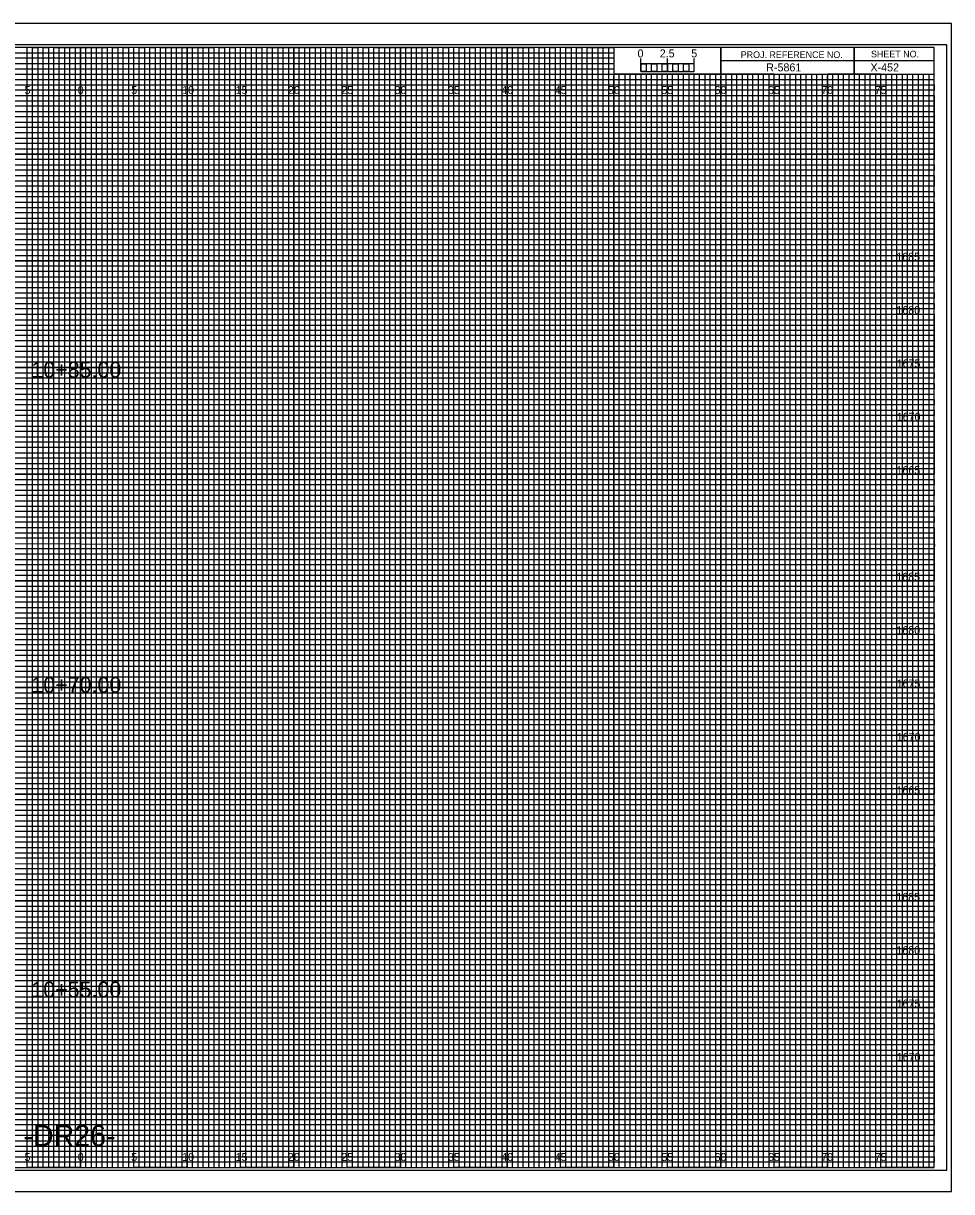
# Model space of a CAD drawing. Extents: x -7 to 162, y -2 to 217.
# Drawn here: x 74.6 to 161.7, y -2.3 to 107.3 of the extents above; entities that cross this region are included whole.
import ezdxf

# ---------------------------------------------------------------- set-up
doc = ezdxf.new("R2010")
doc.units = 0
for name, color, linetype in [('Prop Horizontal Alignment', 7, 'Continuous'), ('Prop XS Alignment Label', 7, 'Continuous'), ('Prop XS Bar Scale Labels', 7, 'Continuous'), ('Prop XS Project Number', 7, 'Continuous'), ('Prop XS Sheet Number', 7, 'Continuous'), ('Raster_Level_0', 7, 'Continuous'), ('Scratch_Level_3', 7, 'Continuous'), ('Sheet Cross Section CELL', 7, 'Continuous'), ('Sheet Cross Section Grid Major CELL', 7, 'Continuous'), ('Sheet Cross Section Grid Middle CELL', 7, 'Continuous'), ('Sheet Cross Section Grid Minor 1 CELL', 7, 'Continuous'), ('Sheet Cross Section Grid Minor 2 CELL', 7, 'Continuous'), ('Sheet Cross Section Scale CELL', 7, 'Continuous'), ('Sheet Cutting Line CELL', 7, 'Continuous'), ('Sheet DOT Grid CELL', 7, 'Continuous'), ('Sheet Plot Border Inside CELL', 7, 'Continuous'), ('Sheet Plot Border Outside CELL', 7, 'Continuous')]:
    doc.layers.add(name, color=color, linetype=linetype)

msp = doc.modelspace()

# ---------------------------------------------------------------- linework, layer by layer
at = {"layer": 'Sheet Cross Section CELL'}
for p, q in [((152.5, 105), (152.5, 102.5)), ((152.5, 102.5), (152.5, 105)), ((160, 103.75), (140, 103.75)), ((140, 103.75), (140, 102.5)), ((140, 102.5), (160, 102.5))]:
    msp.add_line(p, q, dxfattribs=at)
for points in [[(160, 105), (0, 105), (0, 0), (160, 0)], [(140, 105), (130, 105), (130, 102.52), (140, 102.52)], [(160, 105), (140, 105), (140, 102.5), (160, 102.5)]]:
    msp.add_lwpolyline(points, close=True, dxfattribs=at)
at = {"layer": 'Sheet Cross Section Grid Major CELL'}
for p, q in [((75, 105), (70, 105)), ((75, 0), (75, 105)), ((85, 105), (80, 105)), ((80, 105), (80, 0)), ((85, 0), (85, 105)), ((95, 105), (90, 105)), ((90, 105), (90, 0)), ((95, 0), (95, 105)), ((105, 105), (100, 105)), ((100, 105), (100, 0)), ((105, 0), (105, 105)), ((115, 105), (110, 105)), ((110, 105), (110, 0)), ((115, 0), (115, 105)), ((125, 105), (120, 105)), ((120, 105), (120, 0)), ((125, 0), (125, 105)), ((130, 105), (130, 0)), ((135, 0), (135, 102.5)), ((145, 102.5), (140, 102.5)), ((140, 102.5), (140, 0)), ((145, 0), (145, 102.5)), ((155, 102.5), (150, 102.5)), ((150, 102.5), (150, 0)), ((155, 0), (155, 102.5)), ((80, 0), (75, 0)), ((90, 0), (85, 0)), ((100, 0), (95, 0)), ((110, 0), (105, 0)), ((120, 0), (115, 0)), ((130, 0), (125, 0)), ((140, 0), (135, 0)), ((150, 0), (145, 0)), ((160, 0), (155, 0)), ((160, 0), (160, 0))]:
    msp.add_line(p, q, dxfattribs=at)
for points in [[(0, 100), (160, 100), (160, 95), (0, 95)], [(0, 90), (160, 90), (160, 85), (0, 85)], [(0, 80), (160, 80), (160, 75), (0, 75)], [(0, 70), (160, 70), (160, 65), (0, 65)], [(0, 60), (160, 60), (160, 55), (0, 55)], [(0, 50), (160, 50), (160, 45), (0, 45)], [(0, 40), (160, 40), (160, 35), (0, 35)], [(0, 30), (160, 30), (160, 25), (0, 25)], [(0, 20), (160, 20), (160, 15), (0, 15)], [(0, 10), (160, 10), (160, 5), (0, 5)]]:
    msp.add_lwpolyline(points, dxfattribs=at)
at = {"layer": 'Sheet Cross Section Grid Middle CELL'}
for points in [[(72.5, 0), (77.5, 0), (77.5, 105), (82.5, 105), (82.5, 0), (87.5, 0), (87.5, 105), (92.5, 105), (92.5, 0), (97.5, 0), (97.5, 105), (102.5, 105), (102.5, 0), (107.5, 0), (107.5, 105), (112.5, 105), (112.5, 0), (117.5, 0), (117.5, 105), (122.5, 105), (122.5, 0), (127.5, 0), (127.5, 105), (129.97, 105), (130, 105), (130, 102.5), (132.5, 102.5), (132.5, 0), (137.5, 0), (137.5, 102.5), (142.5, 102.5), (142.5, 0), (147.5, 0), (147.5, 102.5), (152.5, 102.5), (152.5, 0), (157.5, 0), (157.5, 102.5)], [(0, 102.5), (137.5, 102.5)], [(0, 92.5), (160, 92.5), (160, 97.5), (0, 97.5)], [(0, 82.5), (160, 82.5), (160, 87.5), (0, 87.5)], [(0, 72.5), (160, 72.5), (160, 77.5), (0, 77.5)], [(0, 62.5), (160, 62.5), (160, 67.5), (0, 67.5)], [(0, 52.5), (160, 52.5), (160, 57.5), (0, 57.5)], [(0, 42.5), (160, 42.5), (160, 47.5), (0, 47.5)], [(0, 32.5), (160, 32.5), (160, 37.5), (0, 37.5)], [(0, 22.5), (160, 22.5), (160, 27.5), (0, 27.5)], [(0, 12.5), (160, 12.5), (160, 17.5), (0, 17.5)], [(0, 2.5), (160, 2.5), (160, 7.5), (0, 7.5)]]:
    msp.add_lwpolyline(points, dxfattribs=at)
at = {"layer": 'Sheet Cross Section Grid Minor 1 CELL'}
for p, q in [((0, 104.5), (130, 104.5)), ((130, 104.5), (130, 103.99)), ((130, 103.99), (0, 103.99)), ((0, 103.5), (130, 103.5)), ((130, 102.95), (0, 102.95)), ((130, 103.5), (130, 102.95)), ((0, 102), (160, 102))]:
    msp.add_line(p, q, dxfattribs=at)
for points in [[(0, 101.5), (135, 101.5), (160, 101.5), (160, 101), (0, 101)], [(0, 100.5), (160, 100.5), (160, 99.5), (0, 99.5)], [(0, 99), (160, 99), (160, 98.5), (0, 98.49)], [(0, 98), (160, 98), (160, 97), (0, 97)], [(0, 96.5), (160, 96.5), (160, 96), (0, 96)], [(0, 95.5), (160, 95.5), (160, 94.5), (0, 94.5)], [(0, 94), (160, 94), (160, 93.5), (0, 93.5)], [(0, 93), (160, 93), (160, 92), (0, 92)], [(0, 91.5), (160, 91.5), (160, 91), (0, 91)], [(0, 90.5), (160, 90.5), (160, 89.5), (0, 89.5)], [(0, 89), (160, 89), (160, 88.5), (0, 88.5)], [(0, 88), (160, 88), (160, 86.98), (160, 86.5), (160, 86), (0, 86)], [(0, 87), (160, 87), (160, 86.5), (0, 86.5)], [(0, 85.5), (160, 85.5), (160, 84.5), (0, 84.52)], [(0, 84.52), (160, 84.5), (160, 84), (0, 84)], [(0, 83.5), (160, 83.5), (160, 83), (0, 83)], [(0, 82), (160, 82), (160, 81.5), (0, 81.5)], [(0, 81), (160, 81), (160, 80.5), (0, 80.5)], [(-0.04, 79.45), (160, 79.45), (160, 78.94), (-0.04, 78.94)], [(0, 78.5), (160, 78.5), (160, 78), (0, 78)], [(0, 77), (160, 77), (160, 76.5), (0, 76.5)], [(0, 76), (160, 76), (160, 75.5), (0, 75.5)], [(0, 74.5), (160, 74.5), (160, 74), (0, 74)], [(0, 73.5), (160, 73.5), (160, 73), (0, 73)], [(0, 72), (160, 72), (160, 71.5), (0, 71.5)], [(0, 71), (160, 71), (160, 70.5), (0, 70.5)], [(0, 69.5), (160, 69.5), (160, 68.99), (0, 69)], [(0, 68.5), (160, 68.5), (160, 68), (0, 68)], [(0, 67), (160, 67), (160, 66.5), (0, 66.5)], [(0, 66), (160, 66), (160, 65.5), (0, 65.5)], [(0, 64.5), (160, 64.5), (160, 64), (0, 64)], [(0, 63.5), (160, 63.5), (160, 63), (0, 63)], [(0, 62), (160, 62), (160, 61.5), (0, 61.5)], [(0, 61), (160, 61), (160, 60.5), (0, 60.5)], [(0, 59.5), (160, 59.5), (160, 59), (0, 59)], [(0, 58.5), (160.03, 58.45), (160, 58), (0, 58)], [(0, 57), (160, 57), (160, 56.5), (0, 56.5)], [(0, 56), (160, 56), (160, 55.5), (0, 55.5)], [(0, 54.5), (160, 54.5), (160, 54), (0, 54)], [(0, 53.5), (160, 53.5), (160, 53), (0, 53)], [(0, 52), (160, 52), (160, 51.5), (0, 51.5)], [(0, 51), (160, 51), (160, 50.5), (0, 50.5)], [(0, 49.5), (160, 49.5), (160, 49), (0, 49)], [(0, 48.5), (160, 48.5), (160, 48), (0, 48)], [(0, 47), (160, 47), (160, 46.5), (0, 46.5)], [(0, 46), (160, 46), (160, 45.5), (0, 45.5)], [(0, 44.5), (160, 44.5), (160, 44), (0, 44)], [(0, 43.5), (160, 43.5), (160, 43), (0, 43)], [(0, 42), (160, 42), (160, 41.5), (0, 41.5)], [(0, 41), (160, 41), (160, 40.5), (0, 40.5)], [(0, 39.5), (160, 39.5), (160, 38.99), (0, 39)], [(0, 38.5), (160, 38.5), (160, 38), (0, 38)], [(0, 37), (160, 37), (160, 36.5), (0, 36.5)], [(0, 36), (160, 36), (160, 35.5), (0, 35.5)], [(0, 34.5), (160, 34.5), (160, 34), (0, 34)], [(0, 33.5), (160, 33.5), (160, 33), (0, 33)], [(0, 32), (160, 32), (160, 31.5), (0, 31.5)], [(0, 31), (160, 31), (160, 30.5), (0, 30.5)], [(0, 29.5), (160, 29.5), (160, 29), (0, 29)], [(0, 28.5), (160.03, 28.46), (160, 28), (0, 28)], [(0, 27), (160, 27), (160, 26.5), (0, 26.5)], [(0, 26), (160, 26), (160, 25.5), (0, 25.5)], [(0, 24.5), (160, 24.5), (160, 24), (0, 24)], [(0, 23.5), (160, 23.5), (160, 23), (0, 23)], [(0, 22), (160, 22), (160, 21.5), (0, 21.5)], [(0, 21), (160, 21), (160, 20.5), (0, 20.5)], [(0, 19.5), (160, 19.5), (160, 19), (0, 19)], [(0, 18.5), (160, 18.5), (160, 18), (0, 18)], [(0, 17), (160, 17), (160, 16.5), (0, 16.5)], [(0, 16), (160, 16), (160, 15.5), (0, 15.5)], [(0, 14.5), (160, 14.5), (160, 14), (0, 14)], [(0, 13.5), (160, 13.5), (160, 13), (0, 13)], [(0, 12), (160, 12), (160, 11.5), (0, 11.5)], [(0, 11), (160, 11), (160, 10.5), (0, 10.5)], [(0, 9.5), (160, 9.5), (160, 9), (0, 9)], [(0, 8.5), (160, 8.5), (160, 8), (0, 8)], [(0, 7), (160, 7), (160, 6.5), (0, 6.5)], [(0, 6), (160, 6), (160, 5.5), (0, 5.5)], [(0, 4.5), (160, 4.5), (160, 4), (0, 4)], [(0, 3.5), (160, 3.5), (160, 3), (0, 3)], [(0, 2), (160, 2), (160, 1.5), (0, 1.5)], [(0, 1), (160, 1), (160, 0.5), (0, 0.5)]]:
    msp.add_lwpolyline(points, dxfattribs=at)
at = {"layer": 'Sheet Cross Section Grid Minor 2 CELL'}
for p, q in [((133.5, 102.5), (133, 102.5)), ((133, 102.5), (133, 0)), ((133.5, 0), (133.5, 102.5)), ((134.5, 102.5), (134, 102.5)), ((134, 102.5), (134, 0)), ((134.5, 0), (134.5, 102.5)), ((133, 0), (132.5, 0)), ((134, 0), (133.5, 0))]:
    msp.add_line(p, q, dxfattribs=at)
for points in [[(75, 0), (75.5, 0), (75.5, 105), (76, 105), (76, 0)], [(76, 0), (76.5, 0), (76.5, 105), (77, 105), (77, 0)], [(77.5, 0), (78, 0), (78, 105), (78.5, 105), (78.5, 0)], [(78.5, 0), (79, 0), (79, 105), (79.5, 105), (79.5, 0)], [(80, 0), (80.5, 0), (80.5, 105), (81, 105), (81, 0)], [(81, 0), (81.5, 0), (81.5, 105), (82, 105), (82, 0)], [(82.5, 0), (83, 0), (83, 105), (83.5, 105), (83.5, 0)], [(83.5, 0), (84, 0), (84, 105), (84.5, 105), (84.5, 0)], [(85, 0), (85.5, 0), (85.5, 105), (86, 105), (86, 0)], [(86, 0), (86.5, 0), (86.5, 105), (87, 105), (87, 0)], [(87.5, 0), (88, 0), (88, 105), (88.5, 105), (88.5, 0)], [(88.5, 0), (89, 0), (89, 105), (89.5, 105), (89.5, 0)], [(90, 0), (90.5, 0), (90.5, 105), (91, 105), (91, 0)], [(91, 0), (91.5, 0), (91.5, 105), (92, 105), (92, 0)], [(92.5, 0), (93, 0), (93, 105), (93.5, 105), (93.5, 0)], [(93.5, 0), (94, 0), (94, 105), (94.5, 105), (94.5, 0)], [(95, 0), (95.5, 0), (95.5, 105), (96, 105), (96, 0)], [(96, 0), (96.5, 0), (96.5, 105), (97, 105), (97, 0)], [(97.5, 0), (98, 0), (98, 105), (98.5, 105), (98.5, 0)], [(98.5, 0), (99, 0), (99, 105), (99.5, 105), (99.5, 0)], [(100, 0), (100.5, 0), (100.5, 105), (101, 105), (101, 0)], [(101, 0), (101.5, 0), (101.5, 105), (102, 105), (102, 0)], [(102.5, 0), (103, 0), (103, 105), (103.5, 105), (103.5, 0)], [(103.5, 0), (104, 0), (104, 105), (104.5, 105), (104.5, 0)], [(105, 0), (105.5, 0), (105.5, 105), (106, 105), (106, 0)], [(106, 0), (106.5, 0), (106.5, 105), (107, 105), (107, 0)], [(107.5, 0), (108, 0), (108, 105), (108.5, 105), (108.5, 0)], [(108.5, 0), (109, 0), (109, 105), (109.5, 105), (109.5, 0)], [(110, 0), (110.5, 0), (110.5, 105), (111, 105), (111, 0)], [(111, 0), (111.5, 0), (111.5, 105), (112, 105), (112, 0)], [(112.5, 0), (113, 0), (113, 105), (113.5, 105), (113.5, 0)], [(113.5, 0), (114, 0), (114, 105), (114.5, 105), (114.5, 0)], [(115, 0), (115.5, 0), (115.5, 105), (116, 105), (116, 0)], [(116, 0), (116.5, 0), (116.5, 105), (117, 105), (117, 0)], [(117.5, 0), (118, 0), (118, 105), (118.5, 105), (118.5, 0)], [(118.5, 0), (119, 0), (119, 105), (119.5, 105), (119.5, 0)], [(120, 0), (120.5, 0), (120.5, 105), (121, 105), (121, 0)], [(121, 0), (121.5, 0), (121.5, 105), (122, 105), (122, 0)], [(122.5, 0), (123, 0), (123, 105), (123.5, 105), (123.5, 0)], [(123.5, 0), (124, 0), (124, 105), (124.5, 105), (124.5, 0)], [(125, 0), (125.5, 0), (125.5, 105), (126, 105), (126, 0)], [(126, 0), (126.5, 0), (126.5, 105), (127, 105), (127, 0)], [(127.5, 0), (128, 0), (128, 105), (128.5, 105), (128.5, 0)], [(128.5, 0), (129, 0), (129, 105), (129.5, 105), (129.5, 0)], [(130, 0), (130.5, 0), (130.5, 102.5), (131.01, 102.5), (131.01, 0)], [(131, 0), (131.5, 0), (131.5, 102.5), (132, 102.5), (132, 0)], [(135, 0), (135.49, 0), (135.49, 102.5), (136, 102.5), (136, 0)], [(136, 0), (136.5, 0), (136.5, 102.5), (137.03, 102.5), (137.03, 0)], [(137.5, 0), (138, 0), (138, 102.5), (138.5, 102.5), (138.5, 0)], [(138.5, 0), (139, 0), (139, 102.5), (139.5, 102.5), (139.5, 0)], [(140, 0), (140.5, 0), (140.5, 102.5), (141, 102.5), (141, 0)], [(141, 0), (141.5, 0), (141.5, 102.5), (142, 102.5), (142, 0)], [(142.5, 0), (143, 0), (143, 102.5), (143.5, 102.5), (143.5, 0)], [(143.5, 0), (144, 0), (144, 102.5), (144.5, 102.5), (144.5, 0)], [(145, 0), (145.5, 0), (145.5, 102.5), (146, 102.5), (146, 0)], [(146, 0), (146.5, 0), (146.5, 102.5), (147, 102.5), (147, 0)], [(147.5, 0), (148, 0), (148, 102.5), (148.5, 102.5), (148.5, 0)], [(148.5, 0), (149, 0), (149, 102.5), (149.5, 102.5), (149.5, 0)], [(150, 0), (150.5, 0), (150.5, 102.5), (151, 102.5), (151, 0)], [(151, 0), (151.5, 0), (151.5, 102.5), (152, 102.5), (152, 0)], [(152.5, 0), (153, 0), (153, 102.5), (153.5, 102.5), (153.5, 0)], [(153.5, 0), (154, 0), (154, 102.5), (154.5, 102.5), (154.5, 0)], [(155, 0), (155.5, 0), (155.5, 102.5), (156, 102.5), (156, 0)], [(156, 0), (156.5, 0), (156.5, 102.5), (157, 102.5), (157, 0)], [(157.5, 0), (158, 0), (158, 102.5), (158.5, 102.5), (158.5, 0)], [(158.5, 0), (159, 0), (159, 102.5), (159.5, 102.5), (159.5, 0)]]:
    msp.add_lwpolyline(points, dxfattribs=at)
at = {"layer": 'Sheet Cross Section Scale CELL'}
for p, q in [((132.5, 102.75), (132.5, 103.95)), ((132.5, 103.45), (132.5, 103.95)), ((135, 102.75), (135, 103.95)), ((137.5, 102.75), (137.5, 103.95)), ((137.5, 103.45), (137.5, 103.95))]:
    msp.add_line(p, q, dxfattribs=at)
for points in [[(137.5, 103.45), (132.5, 103.45), (132.5, 102.75), (137.5, 102.75)], [(132.5, 103.45), (133, 103.45), (133, 102.75), (132.5, 102.75)], [(133.5, 103.45), (134, 103.45), (134, 102.75), (133.5, 102.75)], [(134.5, 103.45), (135, 103.45), (135, 102.75), (134.5, 102.75)], [(135.5, 103.45), (136, 103.45), (136, 102.75), (135.5, 102.75)], [(136.5, 103.45), (137, 103.45), (137, 102.75), (136.5, 102.75)]]:
    msp.add_lwpolyline(points, close=True, dxfattribs=at)
at = {"layer": 'Sheet Cutting Line CELL'}
for p, q in [((161.65, 107.25), (-6.7, 107.25)), ((-6.7, -2.25), (161.65, -2.25))]:
    msp.add_line(p, q, dxfattribs=at)
at = {"layer": 'Sheet DOT Grid CELL'}
for p, q in [((75, 0), (75, 105)), ((80, 0), (80, 105)), ((85, 0), (85, 105)), ((90, 0), (90, 105)), ((95, 0), (95, 105)), ((100, 0), (100, 105)), ((105, 0), (105, 105)), ((110, 0), (110, 105)), ((115, 0), (115, 105)), ((120, 0), (120, 105)), ((125, 0), (125, 105)), ((130, 0), (130, 102.34)), ((135, 0), (135, 102.34)), ((140, 0), (140, 102.34)), ((145, 0), (145, 102.34)), ((150, 0), (150, 102.34)), ((155, 0), (155, 102.34)), ((0, 100), (160, 100)), ((0, 95), (160, 95)), ((0, 90), (160, 90)), ((0, 85), (160, 85)), ((0, 80), (160, 80)), ((0, 75), (160, 75)), ((0, 70), (160, 70)), ((0, 65), (160, 65)), ((0, 60), (160, 60)), ((0, 55), (160, 55)), ((0, 50), (160, 50)), ((0, 45), (160, 45)), ((0, 40), (160, 40)), ((0, 35), (160, 35)), ((0, 30), (160, 30)), ((0, 25), (160, 25)), ((0, 20), (160, 20)), ((0, 15), (160, 15)), ((0, 10), (160, 10)), ((0, 5), (160, 5))]:
    msp.add_line(p, q, dxfattribs=at)
at = {"layer": 'Sheet Plot Border Inside CELL'}
msp.add_lwpolyline([(-5.4, -0.25), (161.2, -0.25), (161.2, 105.25), (-5.4, 105.25)], close=True, dxfattribs=at)
at = {"layer": 'Sheet Plot Border Outside CELL'}
msp.add_lwpolyline([(-6.7, -2.25), (161.65, -2.25), (161.65, 107.25), (-6.7, 107.25)], close=True, dxfattribs=at)

# ---------------------------------------------------------------- texts
at = {"layer": 'Prop Horizontal Alignment'}
for s, p in [('10+85.00', (75.39, 74.04)), ('10+70.00', (75.39, 44.5)), ('10+55.00', (75.39, 15.94))]:
    msp.add_text(s, height=1.5, dxfattribs=at).set_placement(p)
at = {"layer": 'Prop XS Alignment Label'}
msp.add_text('-DR26-', height=2, dxfattribs=at).set_placement((74.65, 2))
at = {"layer": 'Prop XS Bar Scale Labels'}
for s, p in [('2.5', (134.29, 104.06)), ('5', (137.24, 104.06))]:
    msp.add_text(s, height=0.75, dxfattribs=at).set_placement(p)
at = {"layer": 'Prop XS Project Number'}
msp.add_text('R-5861', height=0.75, dxfattribs=at).set_placement((144.27, 102.75))
at = {"layer": 'Prop XS Sheet Number'}
msp.add_text('X-452', height=0.75, dxfattribs=at).set_placement((154.04, 102.75))
at = {"layer": 'Raster_Level_0'}
for s, p in [('5', (74.74, 100.62)), ('0', (79.73, 100.62)), ('0', (79.73, 100.62)), ('5', (84.74, 100.62)), ('10', (89.52, 100.62)), ('15', (94.53, 100.62)), ('20', (99.43, 100.62)), ('25', (104.44, 100.62)), ('30', (109.43, 100.62)), ('35', (114.44, 100.62)), ('40', (119.43, 100.62)), ('45', (124.44, 100.62)), ('50', (129.43, 100.62)), ('55', (134.44, 100.62)), ('60', (139.43, 100.62)), ('65', (144.44, 100.62)), ('70', (149.43, 100.62)), ('75', (154.44, 100.62)), ('5', (74.74, 0.62)), ('0', (79.73, 0.62)), ('0', (79.73, 0.62)), ('5', (84.74, 0.62)), ('10', (89.52, 0.62)), ('15', (94.53, 0.62)), ('20', (99.43, 0.62)), ('25', (104.44, 0.62)), ('30', (109.43, 0.62)), ('35', (114.44, 0.62)), ('40', (119.43, 0.62)), ('45', (124.44, 0.62)), ('50', (129.43, 0.62)), ('55', (134.44, 0.62)), ('60', (139.43, 0.62)), ('65', (144.44, 0.62)), ('70', (149.43, 0.62)), ('75', (154.44, 0.62))]:
    msp.add_text(s, height=0.75, dxfattribs=at).set_placement(p)
at = {"layer": 'Scratch_Level_3'}
for s, p in [('1685', (156.46, 85)), ('1680', (156.47, 80)), ('1675', (156.49, 75)), ('1670', (156.5, 70)), ('1665', (156.48, 65)), ('1685', (156.46, 55)), ('1680', (156.47, 50)), ('1675', (156.49, 45)), ('1670', (156.5, 40)), ('1665', (156.48, 35)), ('1685', (156.46, 25)), ('1680', (156.47, 20)), ('1675', (156.49, 15)), ('1670', (156.5, 10))]:
    msp.add_text(s, height=0.75, dxfattribs=at).set_placement(p)
at = {"layer": 'Sheet Cross Section CELL'}
for s, p in [('PROJ. REFERENCE NO.', (141.88, 104)), ('SHEET NO.', (154.09, 104.06))]:
    msp.add_text(s, height=0.625, dxfattribs=at).set_placement(p)
at = {"layer": 'Sheet Cross Section Scale CELL'}
msp.add_text('0', height=0.75, dxfattribs=at).set_placement((132.21, 104.06))

doc.saveas('drawing.dxf')
